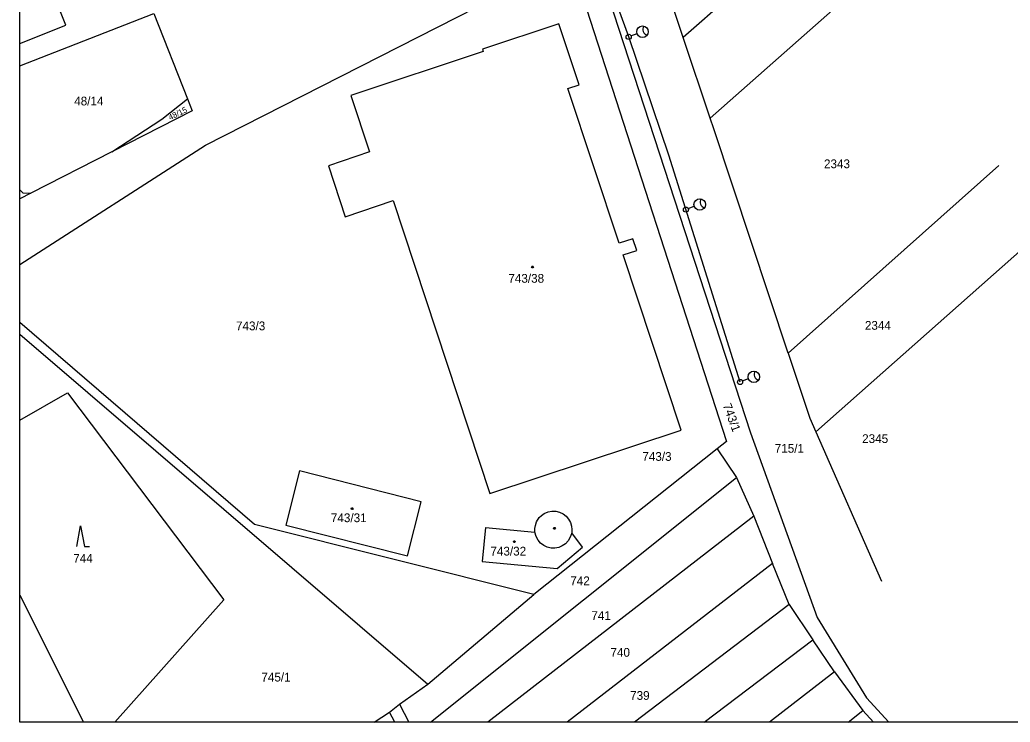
# Model space of a CAD drawing. Extents: x -639590 to -639298, y -1193269 to -1192863.
# Drawn here: x -639590.4 to -639398, y -1193268.8 to -1193132.4 of the extents above; entities that cross this region are included whole.
import ezdxf

# ---------------------------------------------------------------- set-up
doc = ezdxf.new("R2010")
doc.units = 0
for name, color, linetype in [('Vrstva 1', 7, 'Continuous'), ('Vrstva 2', 7, 'Continuous'), ('Vrstva 22', 7, 'Continuous'), ('Vrstva 3', 7, 'Continuous'), ('Vrstva 4', 7, 'Continuous'), ('Vrstva 5', 7, 'Continuous'), ('Vrstva 61', 7, 'Continuous')]:
    doc.layers.add(name, color=color, linetype=linetype)

msp = doc.modelspace()

# ---------------------------------------------------------------- linework, layer by layer
at = {"layer": 'Vrstva 1'}
for p, q in [((-639400.3, -1193081.78), (-639461.48, -1193135.8)), ((-639486.01, -1193097.33), (-639448.4, -1193212.6)), ((-639411.59, -1193111.93), (-639456.25, -1193151.46)), ((-639554.34, -1193156.7), (-639483.37, -1193120.58)), ((-639483.37, -1193120.58), (-639453.06, -1193214.27)), ((-639461.48, -1193135.8), (-639466.59, -1193120.49)), ((-639581.47, -1193133.39), (-639585, -1193124.36)), ((-639590.39, -1193141.32), (-639564.32, -1193131.1)), ((-639564.32, -1193131.1), (-639557.8, -1193147.72)), ((-639590.39, -1193136.94), (-639581.47, -1193133.39)), ((-639485.63, -1193133.13), (-639500.51, -1193138.07)), ((-639481.7, -1193144.98), (-639485.63, -1193133.13)), ((-639456.25, -1193151.46), (-639461.48, -1193135.8)), ((-639500.51, -1193138.07), (-639500.37, -1193138.49)), ((-639500.37, -1193138.49), (-639526.08, -1193147.06)), ((-639483.88, -1193145.7), (-639481.7, -1193144.98)), ((-639473.92, -1193175.75), (-639483.88, -1193145.7)), ((-639526.08, -1193147.06), (-639522.43, -1193158.01)), ((-639562.77, -1193151.67), (-639557.8, -1193147.72)), ((-639557.8, -1193147.72), (-639556.9, -1193150.01)), ((-639556.9, -1193150.01), (-639572.53, -1193157.99)), ((-639455.57, -1193153.51), (-639456.25, -1193151.46)), ((-639572.53, -1193157.99), (-639562.77, -1193151.67)), ((-639441.09, -1193197.09), (-639455.57, -1193153.51)), ((-639590.39, -1193179.89), (-639554.34, -1193156.7)), ((-639572.53, -1193157.99), (-639588.28, -1193166.02)), ((-639522.43, -1193158.01), (-639530.44, -1193160.7)), ((-639530.44, -1193160.7), (-639527.19, -1193170.59)), ((-639400.2, -1193160.62), (-639441.09, -1193197.09)), ((-639590.39, -1193165.4), (-639589.78, -1193165.93)), ((-639588.28, -1193166.02), (-639590.39, -1193167.1)), ((-639589.78, -1193165.93), (-639588.28, -1193166.02)), ((-639527.19, -1193170.59), (-639517.87, -1193167.48)), ((-639517.87, -1193167.48), (-639499.04, -1193224.37)), ((-639471.27, -1193174.87), (-639473.92, -1193175.75)), ((-639470.51, -1193177.15), (-639471.27, -1193174.87)), ((-639435.74, -1193212.36), (-639394.97, -1193176.34)), ((-639473.17, -1193178.03), (-639470.51, -1193177.15)), ((-639461.88, -1193212.05), (-639473.17, -1193178.03)), ((-639544.82, -1193230.4), (-639590.39, -1193191.14)), ((-639590.39, -1193193.39), (-639511.13, -1193261.36)), ((-639441.09, -1193197.09), (-639436.9, -1193209.72)), ((-639590.39, -1193210.13), (-639581.12, -1193204.81)), ((-639581.12, -1193204.81), (-639550.73, -1193245.01)), ((-639436.9, -1193209.72), (-639435.74, -1193212.36)), ((-639499.04, -1193224.37), (-639461.88, -1193212.05)), ((-639448.4, -1193212.6), (-639435.44, -1193248.47)), ((-639435.74, -1193212.36), (-639422.96, -1193241.4)), ((-639453.06, -1193214.27), (-639454.87, -1193215.71)), ((-639454.87, -1193215.71), (-639490.49, -1193243.94)), ((-639454.87, -1193215.71), (-639451.12, -1193221.27)), ((-639536.05, -1193219.98), (-639538.68, -1193230.5)), ((-639512.42, -1193225.96), (-639536.05, -1193219.98)), ((-639510.58, -1193268.77), (-639451.12, -1193221.27)), ((-639451.12, -1193221.27), (-639447.8, -1193228.76)), ((-639515.08, -1193236.47), (-639512.42, -1193225.96)), ((-639489.04, -1193228.6), (-639488.51, -1193228.26)), ((-639488.51, -1193228.26), (-639487.75, -1193227.92)), ((-639487.75, -1193227.92), (-639487.01, -1193227.78)), ((-639487.01, -1193227.78), (-639486.26, -1193227.8)), ((-639486.26, -1193227.8), (-639485.52, -1193227.98)), ((-639485.52, -1193227.98), (-639484.84, -1193228.3)), ((-639484.84, -1193228.3), (-639484.25, -1193228.75)), ((-639490.49, -1193243.94), (-639544.82, -1193230.4)), ((-639447.8, -1193228.76), (-639499.44, -1193268.77)), ((-639490.22, -1193230.54), (-639489.97, -1193229.83)), ((-639489.97, -1193229.83), (-639489.45, -1193229.01)), ((-639489.45, -1193229.01), (-639489.04, -1193228.6)), ((-639484.25, -1193228.75), (-639483.76, -1193229.33)), ((-639483.76, -1193229.33), (-639483.4, -1193229.99)), ((-639483.4, -1193229.99), (-639483.18, -1193230.71)), ((-639447.8, -1193228.76), (-639444.12, -1193237.92)), ((-639538.68, -1193230.5), (-639515.08, -1193236.47)), ((-639499.92, -1193230.97), (-639500.54, -1193237.59)), ((-639499.92, -1193230.97), (-639490.31, -1193231.87)), ((-639490.31, -1193231.18), (-639490.22, -1193230.54)), ((-639490.31, -1193231.87), (-639490.31, -1193231.18)), ((-639483.18, -1193230.71), (-639483.12, -1193231.32)), ((-639483.12, -1193231.32), (-639483.12, -1193231.98)), ((-639481.04, -1193234.75), (-639483.12, -1193231.98)), ((-639486.01, -1193238.95), (-639481.04, -1193234.75)), ((-639500.54, -1193237.59), (-639486.01, -1193238.95)), ((-639444.12, -1193237.92), (-639484.06, -1193268.77)), ((-639440.91, -1193245.9), (-639444.12, -1193237.92)), ((-639590.39, -1193244.13), (-639578, -1193268.77)), ((-639550.73, -1193245.01), (-639571.95, -1193268.77)), ((-639511.13, -1193261.36), (-639490.49, -1193243.94)), ((-639440.91, -1193245.9), (-639470.97, -1193268.77)), ((-639440.91, -1193245.9), (-639436.28, -1193252.77)), ((-639435.44, -1193248.47), (-639425.91, -1193264.07)), ((-639457.4, -1193268.77), (-639436.28, -1193252.77)), ((-639432.11, -1193258.97), (-639436.28, -1193252.77)), ((-639432.11, -1193258.97), (-639444.72, -1193268.77)), ((-639432.11, -1193258.97), (-639426.57, -1193266.5)), ((-639516.59, -1193265.27), (-639511.13, -1193261.36)), ((-639425.91, -1193264.07), (-639421.55, -1193268.77)), ((-639521.53, -1193268.77), (-639518.54, -1193266.82)), ((-639518.54, -1193266.82), (-639516.59, -1193265.27)), ((-639517.54, -1193268.77), (-639518.54, -1193266.82)), ((-639516.59, -1193265.27), (-639514.8, -1193268.77)), ((-639429.45, -1193268.77), (-639426.57, -1193266.5)), ((-639426.57, -1193266.5), (-639424.5, -1193268.77)), ((-639546.37, -1193268.77), (-639546.37, -1193268.77)), ((-639546.37, -1193268.77), (-639546.37, -1193268.77))]:
    msp.add_line(p, q, dxfattribs=at)
at = {"layer": 'Vrstva 22'}
for p, q in [((-639471.64, -1193135.46), (-639470.47, -1193135.03)), ((-639460.51, -1193169.01), (-639459.35, -1193168.58)), ((-639450, -1193202.48), (-639448.83, -1193202.05))]:
    msp.add_line(p, q, dxfattribs=at)
msp.add_lwpolyline([(-639450.45, -1193202.7), (-639464.28, -1193158.66), (-639472.09, -1193135.67), (-639482.36, -1193107.37)], dxfattribs=at)
for centre, radius in [((-639469.41, -1193134.67), 1.12), ((-639472.09, -1193135.67), 0.5), ((-639460.96, -1193169.22), 0.5), ((-639458.28, -1193168.23), 1.12), ((-639447.77, -1193201.7), 1.12), ((-639450.45, -1193202.7), 0.5)]:
    msp.add_circle(centre, radius, dxfattribs=at)
for centre in [(-639468.21, -1193134.22), (-639457.08, -1193167.78), (-639446.57, -1193201.25)]:
    msp.add_arc(centre, 1.12, 145.2334, 255.9457, dxfattribs=at)
at = {"layer": 'Vrstva 3'}
msp.add_lwpolyline([(-639579.32, -1193234.62), (-639578.57, -1193230.62), (-639577.82, -1193234.62), (-639576.82, -1193234.62)], dxfattribs=at)
at = {"layer": 'Vrstva 4'}
for p, q in [((-639490.05, -1193232.73), (-639490.31, -1193231.87)), ((-639483.12, -1193231.98), (-639483.36, -1193232.69)), ((-639489.68, -1193233.41), (-639490.05, -1193232.73)), ((-639489.19, -1193233.99), (-639489.68, -1193233.41)), ((-639488.6, -1193234.44), (-639489.19, -1193233.99)), ((-639484.38, -1193234.1), (-639485, -1193234.53)), ((-639483.86, -1193233.56), (-639484.38, -1193234.1)), ((-639483.36, -1193232.69), (-639483.86, -1193233.56)), ((-639487.92, -1193234.77), (-639488.6, -1193234.44)), ((-639487.18, -1193234.94), (-639487.92, -1193234.77)), ((-639486.43, -1193234.96), (-639487.18, -1193234.94)), ((-639485.69, -1193234.82), (-639486.43, -1193234.96)), ((-639485, -1193234.53), (-639485.69, -1193234.82))]:
    msp.add_line(p, q, dxfattribs=at)
at = {"layer": 'Vrstva 5'}
for points in [[(-639490.68, -1193180.2), (-639490.59, -1193180.35), (-639490.68, -1193180.5), (-639490.86, -1193180.5), (-639490.95, -1193180.35), (-639490.86, -1193180.2)], [(-639525.74, -1193227.15), (-639525.65, -1193227.3), (-639525.74, -1193227.45), (-639525.92, -1193227.45), (-639526.01, -1193227.3), (-639525.92, -1193227.15)], [(-639486.42, -1193230.98), (-639486.33, -1193231.13), (-639486.42, -1193231.28), (-639486.6, -1193231.28), (-639486.69, -1193231.13), (-639486.6, -1193230.98)], [(-639494.22, -1193233.54), (-639494.13, -1193233.69), (-639494.22, -1193233.84), (-639494.4, -1193233.84), (-639494.49, -1193233.69), (-639494.4, -1193233.54)]]:
    msp.add_lwpolyline(points, close=True, dxfattribs=at)
at = {"layer": 'Vrstva 61'}
for points in [[(-639590.39, -1193268.77), (-639590.39, -1192863.27)], [(-639298.39, -1193268.77), (-639590.39, -1193268.77)]]:
    msp.add_lwpolyline(points, dxfattribs=at)

# ---------------------------------------------------------------- texts
at = {"layer": 'Vrstva 2'}
for s, p in [('48/14', (-639579.82, -1193148.98)), ('2343', (-639434.14, -1193161.17)), ('743/38', (-639495.47, -1193183.42)), ('743/3', (-639548.39, -1193192.65)), ('2344', (-639426.19, -1193192.55)), ('2345', (-639426.73, -1193214.55)), ('715/1', (-639443.71, -1193216.44)), ('743/3', (-639469.44, -1193218.01)), ('743/31', (-639529.95, -1193229.92)), ('744', (-639580.01, -1193237.79)), ('743/32', (-639498.96, -1193236.4)), ('742', (-639483.44, -1193242.16)), ('741', (-639479.35, -1193248.91)), ('740', (-639475.63, -1193256.06)), ('745/1', (-639543.46, -1193260.87)), ('739', (-639471.81, -1193264.43))]:
    msp.add_text(s, height=1.7, dxfattribs=at).set_placement(p)
for s, height, rotation, p in [('48/15', 1.14, 26.2988, (-639561.17, -1193151.9)), ('743/1', 1.7, 290.3392, (-639453.84, -1193207.21))]:
    msp.add_text(s, height=height, rotation=rotation, dxfattribs=at).set_placement(p)

doc.saveas('drawing.dxf')
